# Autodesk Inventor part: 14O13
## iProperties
Created: 2005-05
Part Number: 14O13
Document SubType Name: Modeling
Designer: rfheme
Manufacturer: Standard
Standards Organization: Custom
Description: ECDIS MONITOR 19"TFT NAV. CONS.
Author: rfheme
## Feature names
1. Extrusion1
2. Fillet1
3. Chamfer1
4. Extrusion2
5. Fillet2
6. Extrusion3
7. Extrusion4
8. Fillet3
9. Fillet4
10. Extrusion5
11. Chamfer2
12. Chamfer3
13. Chamfer4
14. Chamfer5
15. Extrusion7
16. Hole1
17. Extrusion8
18. Mirror2
